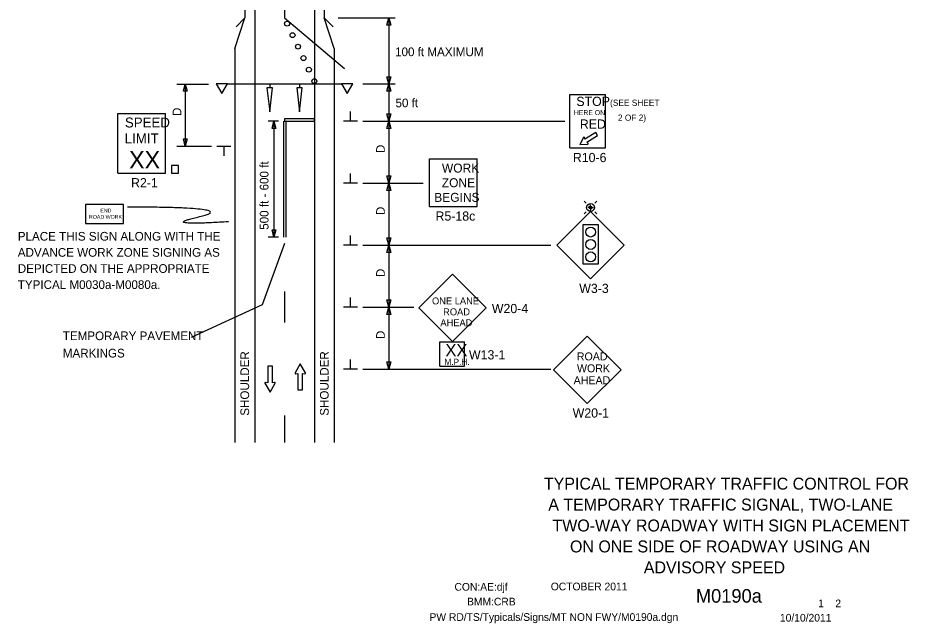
# Model space of a CAD drawing. Extents: x 16739 to 18486, y 7218 to 8208.
# Drawn here: x 16739 to 17457, y 7218 to 7706 of the extents above; entities that cross this region are included whole.
import ezdxf

# ---------------------------------------------------------------- set-up
doc = ezdxf.new("R2010")
doc.units = 0
for name, color, linetype in [('ALI_LEGAL_EX', 7, 'Continuous'), ('BORDER', 7, 'Continuous'), ('BORDER_SIGNAL_WO', 7, 'Continuous'), ('MT_SCRATCH_LEVEL_E', 7, 'Continuous'), ('PAVT_EDGE_EX', 7, 'Continuous'), ('TRAFFIC_SIGNS_PR', 7, 'Continuous'), ('TYPICAL_TEXT_DIMEN_PR', 7, 'Continuous')]:
    doc.layers.add(name, color=color, linetype=linetype)

msp = doc.modelspace()

# ---------------------------------------------------------------- linework, layer by layer
at = {"layer": 'ALI_LEGAL_EX'}
for points in [[(16952.78, 7623.01), (16952.78, 7529.38)], [(16954.78, 7623.01), (16954.78, 7529.38)], [(16953.78, 7485.68), (16953.78, 7460.68)], [(16953.78, 7385.68), (16953.78, 7363.75)]]:
    msp.add_lwpolyline(points, dxfattribs=at)
at = {"layer": 'BORDER'}
msp.add_line((17041.19, 7652.2), (17041.19, 7652.2), dxfattribs=at)
at = {"layer": 'MT_SCRATCH_LEVEL_E'}
for p, q in [((16966.37, 7427.22), (16962.26, 7419.98)), ((16966.37, 7427.22), (16962.26, 7419.98)), ((16970.52, 7419.98), (16966.37, 7427.22)), ((16970.52, 7419.98), (16966.37, 7427.22)), ((16943.98, 7425.26), (16940.24, 7425.26)), ((16940.24, 7425.26), (16940.24, 7412.01)), ((16943.98, 7425.26), (16940.24, 7425.26)), ((16940.24, 7425.26), (16940.24, 7412.01)), ((16943.98, 7412.01), (16943.98, 7425.26)), ((16943.98, 7412.01), (16943.98, 7425.26)), ((16962.74, 7419.29), (16964.52, 7419.61)), ((16962.74, 7419.29), (16964.52, 7419.61)), ((16964.52, 7419.61), (16964.52, 7406.35)), ((16964.52, 7419.61), (16964.52, 7406.35)), ((16968.26, 7406.35), (16968.26, 7419.61)), ((16968.26, 7419.61), (16970.04, 7419.29)), ((16968.26, 7406.35), (16968.26, 7419.61)), ((16968.26, 7419.61), (16970.04, 7419.29)), ((16940.24, 7412.01), (16938.46, 7412.32)), ((16940.24, 7412.01), (16938.46, 7412.32)), ((16945.76, 7412.32), (16943.98, 7412.01)), ((16945.76, 7412.32), (16943.98, 7412.01)), ((16937.98, 7411.64), (16942.13, 7404.4)), ((16937.98, 7411.64), (16942.13, 7404.4)), ((16942.13, 7404.4), (16946.24, 7411.64)), ((16942.13, 7404.4), (16946.24, 7411.64)), ((16964.52, 7406.35), (16968.26, 7406.35)), ((16964.52, 7406.35), (16968.26, 7406.35))]:
    msp.add_line(p, q, dxfattribs=at)
for centre, start, end in [((16962.67, 7419.75), 150.42484, 279.96381), ((16962.67, 7419.75), 150.42484, 279.96381), ((16970.11, 7419.75), 260.03619, 29.77312), ((16970.11, 7419.75), 260.03619, 29.77312), ((16938.39, 7411.86), 80.03619, 209.77312), ((16938.39, 7411.86), 80.03619, 209.77312), ((16945.83, 7411.86), 330.42484, 99.96381), ((16945.83, 7411.86), 330.42484, 99.96381)]:
    msp.add_arc(centre, 0.463, start, end, dxfattribs=at)
at = {"layer": 'PAVT_EDGE_EX'}
for p, q in [((16929.78, 8185.68), (16929.78, 7363.75)), ((16977.78, 8185.68), (16977.78, 7363.75)), ((16921.78, 7837.6), (16921.78, 7706.21)), ((16953.78, 7837.6), (16953.78, 7706.21)), ((16985.78, 7837.6), (16985.78, 7706.21)), ((16913.78, 7681.51), (16921.78, 7706.21)), ((16921.78, 7706.21), (16914.71, 7699.14)), ((16953.78, 7706.21), (17002.19, 7665.59)), ((16985.78, 7706.21), (16992.85, 7699.14)), ((16993.78, 7681.51), (16985.78, 7706.21)), ((16913.78, 7681.51), (16913.78, 7363.75)), ((16993.78, 7681.51), (16993.78, 7363.75))]:
    msp.add_line(p, q, dxfattribs=at)
at = {"layer": 'TRAFFIC_SIGNS_PR'}
for p, q in [((16907.78, 7653.01), (16999.78, 7653.01)), ((16941.78, 7653.01), (16941.78, 7649.99)), ((16965.78, 7653.01), (16965.78, 7649.99)), ((17183.68, 7644.59), (17212.48, 7644.59)), ((17183.68, 7601.39), (17183.68, 7644.59)), ((17198.08, 7644.59), (17198.08, 7644.59)), ((17212.48, 7601.39), (17212.48, 7644.59)), ((16819.37, 7629.06), (16857.77, 7629.06)), ((16819.37, 7581.06), (16819.37, 7629.06)), ((16857.77, 7581.06), (16857.77, 7629.06)), ((17183.68, 7601.39), (17212.48, 7601.39)), ((17070.58, 7554.18), (17070.58, 7592.58)), ((17070.58, 7592.58), (17108.98, 7592.58)), ((17108.98, 7554.18), (17108.98, 7592.58)), ((16819.37, 7581.06), (16857.77, 7581.06)), ((17196.92, 7556.74), (17195.29, 7558.37)), ((17203.77, 7556.74), (17205.39, 7558.37)), ((17070.58, 7554.18), (17108.98, 7554.18)), ((17200.34, 7550.17), (17173.19, 7523.01)), ((17196.92, 7549.89), (17195.29, 7548.27)), ((17200.34, 7553.32), (17198.04, 7553.32)), ((17200.34, 7553.32), (17200.34, 7555.62)), ((17200.34, 7553.32), (17200.34, 7550.17)), ((17200.34, 7553.32), (17202.64, 7553.32)), ((17227.49, 7523.01), (17200.34, 7550.17)), ((17205.39, 7548.27), (17203.77, 7549.89)), ((17173.19, 7523.01), (17200.34, 7495.86)), ((17200.34, 7495.86), (17227.49, 7523.01)), ((17089.01, 7499.48), (17061.85, 7472.33)), ((17116.16, 7472.33), (17089.01, 7499.48)), ((17061.85, 7472.33), (17089.01, 7445.18)), ((17089.01, 7445.18), (17116.16, 7472.33)), ((17197.73, 7449.68), (17170.58, 7422.53)), ((17224.89, 7422.53), (17197.73, 7449.68)), ((17078.98, 7445.12), (17098.83, 7445.12)), ((17078.98, 7425.27), (17078.98, 7445.12)), ((17098.83, 7425.27), (17098.83, 7445.12)), ((17078.98, 7425.27), (17098.83, 7425.27)), ((17170.58, 7422.53), (17197.73, 7395.37)), ((17197.73, 7395.37), (17224.89, 7422.53))]:
    msp.add_line(p, q, dxfattribs=at)
for points in [[(16898.78, 7653.01), (16903.28, 7645.22), (16907.78, 7653.01)], [(16939.53, 7649.99), (16941.78, 7630.57), (16944.03, 7649.99)], [(16963.53, 7649.99), (16965.78, 7630.57), (16968.03, 7649.99)], [(16999.78, 7653.01), (17004.28, 7645.22), (17008.78, 7653.01)], [(16953.78, 7625.01), (16953.78, 7623.01), (16977.78, 7623.01), (16977.78, 7625.01)], [(16862.78, 7581.06), (16868.38, 7581.06), (16868.38, 7587.23), (16862.78, 7587.23)], [(16793.33, 7540.47), (16824.05, 7540.47), (16824.05, 7555.83), (16793.33, 7555.83)], [(17206.4, 7507.56), (17194.4, 7507.56), (17194.4, 7539.56), (17206.4, 7539.56)]]:
    msp.add_lwpolyline(points, close=True, dxfattribs=at)
for points in [[(17198.28, 7605.04), (17197.35, 7606.08), (17206.01, 7611.44), (17204.5, 7613.88), (17195.84, 7608.52), (17195.33, 7609.81)], [(17194.69, 7609.84), (17191.64, 7604.21), (17198.03, 7604.45)]]:
    msp.add_lwpolyline(points, dxfattribs=at)
for centre, radius in [((16955.78, 7701.63), 2), ((16960.18, 7692.37), 2), ((16964.58, 7683.1), 2), ((16968.98, 7673.84), 2), ((16973.38, 7664.57), 2), ((16977.78, 7655.31), 2), ((17200.34, 7553.32), 3.15), ((17200.34, 7553.32), 1.02), ((17200.4, 7533.56), 4), ((17200.4, 7523.56), 4), ((17200.4, 7513.56), 4)]:
    msp.add_circle(centre, radius, dxfattribs=at)
for centre, radius, start, end in [((17195, 7609.67), 0.355, 21.71521, 151.42661), ((17198.01, 7604.8), 0.354, 272.17868, 41.91782)]:
    msp.add_arc(centre, radius, start, end, dxfattribs=at)
msp.add_open_spline([(16908.51, 7541.84), (16850.96, 7538.19), (16918.98, 7553.67), (16827.23, 7553.67)], degree=2, dxfattribs=at)
at = {"layer": 'TYPICAL_TEXT_DIMEN_PR'}
for p, q in [((16997.08, 7706.21), (17042.78, 7706.21)), ((17036.21, 7700.35), (17037.78, 7706.21)), ((17037.78, 7700.35), (17036.21, 7700.35)), ((17037.78, 7706.21), (17037.78, 7653.01)), ((17037.78, 7706.21), (17039.35, 7700.35)), ((17039.35, 7700.35), (17037.78, 7700.35)), ((17037.78, 7653.01), (17036.21, 7658.88)), ((17036.21, 7658.88), (17037.78, 7658.88)), ((17037.78, 7658.88), (17039.35, 7658.88)), ((17039.35, 7658.88), (17037.78, 7653.01)), ((16867.03, 7652.92), (16892.38, 7652.92)), ((16872.21, 7647.06), (16873.78, 7652.92)), ((16873.78, 7652.92), (16873.78, 7602.92)), ((16873.78, 7652.92), (16875.35, 7647.06)), ((17016.78, 7653.01), (17042.78, 7653.01)), ((17036.21, 7647.15), (17037.78, 7653.01)), ((17037.78, 7653.01), (17039.35, 7647.15)), ((17037.78, 7653.01), (17037.78, 7623.01)), ((16873.78, 7647.06), (16872.21, 7647.06)), ((16875.35, 7647.06), (16873.78, 7647.06)), ((17037.78, 7647.15), (17036.21, 7647.15)), ((17039.35, 7647.15), (17037.78, 7647.15)), ((17006.91, 7623.01), (17006.91, 7630.8)), ((17037.78, 7623.01), (17036.21, 7628.88)), ((17036.21, 7628.88), (17037.78, 7628.88)), ((17037.78, 7628.88), (17039.35, 7628.88)), ((17039.35, 7628.88), (17037.78, 7623.01)), ((16948.75, 7623.01), (16940.55, 7623.01)), ((16943.66, 7617.15), (16945.23, 7623.01)), ((16945.23, 7623.01), (16945.23, 7529.38)), ((16945.23, 7623.01), (16946.8, 7617.15)), ((17012.53, 7623.01), (17001.28, 7623.01)), ((17016.78, 7623.01), (17179.49, 7623.01)), ((17036.21, 7617.15), (17037.78, 7623.01)), ((17037.78, 7623.01), (17037.78, 7573.01)), ((17037.78, 7623.01), (17039.35, 7617.15)), ((16945.23, 7617.15), (16943.66, 7617.15)), ((16946.8, 7617.15), (16945.23, 7617.15)), ((17037.78, 7617.15), (17036.21, 7617.15)), ((17039.35, 7617.15), (17037.78, 7617.15)), ((16873.78, 7602.92), (16872.21, 7608.78)), ((16872.21, 7608.78), (16873.78, 7608.78)), ((16873.78, 7608.78), (16875.35, 7608.78)), ((16875.35, 7608.78), (16873.78, 7602.92)), ((16867.03, 7602.92), (16894.99, 7602.92)), ((16899.24, 7602.92), (16910.49, 7602.92)), ((16904.87, 7602.92), (16904.87, 7595.13)), ((17006.91, 7573.01), (17006.91, 7580.8)), ((17037.78, 7573.01), (17036.21, 7578.88)), ((17036.21, 7578.88), (17037.78, 7578.88)), ((17037.78, 7578.88), (17039.35, 7578.88)), ((17039.35, 7578.88), (17037.78, 7573.01)), ((17012.53, 7573.01), (17001.28, 7573.01)), ((17016.78, 7573.01), (17065.34, 7573.01)), ((17036.21, 7567.15), (17037.78, 7573.01)), ((17037.78, 7573.01), (17037.78, 7523.01)), ((17037.78, 7573.01), (17039.35, 7567.15)), ((17037.78, 7567.15), (17036.21, 7567.15)), ((17039.35, 7567.15), (17037.78, 7567.15)), ((16945.23, 7529.38), (16943.66, 7535.25)), ((16943.66, 7535.25), (16945.23, 7535.25)), ((16945.23, 7535.25), (16946.8, 7535.25)), ((16946.8, 7535.25), (16945.23, 7529.38)), ((16948.75, 7529.38), (16940.55, 7529.38)), ((17006.91, 7523.01), (17006.91, 7530.8)), ((17037.78, 7523.01), (17036.21, 7528.88)), ((17036.21, 7528.88), (17037.78, 7528.88)), ((17037.78, 7528.88), (17039.35, 7528.88)), ((17039.35, 7528.88), (17037.78, 7523.01)), ((16936.01, 7475.01), (16953.91, 7524.73)), ((17012.53, 7523.01), (17001.28, 7523.01)), ((17016.78, 7523.01), (17168.45, 7523.01)), ((17036.21, 7517.15), (17037.78, 7523.01)), ((17036.21, 7517.15), (17037.78, 7523.01)), ((17037.78, 7523.01), (17037.78, 7473.01)), ((17037.78, 7523.01), (17039.35, 7517.15)), ((17037.78, 7523.01), (17039.35, 7517.15)), ((17037.78, 7517.15), (17036.21, 7517.15)), ((17037.78, 7517.15), (17036.21, 7517.15)), ((17039.35, 7517.15), (17037.78, 7517.15)), ((17039.35, 7517.15), (17037.78, 7517.15)), ((17006.91, 7473.01), (17006.91, 7480.8)), ((17037.78, 7473.01), (17036.21, 7478.88)), ((17036.21, 7478.88), (17037.78, 7478.88)), ((17037.78, 7478.88), (17039.35, 7478.88)), ((17039.35, 7478.88), (17037.78, 7473.01)), ((16878.77, 7448.84), (16936.01, 7475.01)), ((17012.53, 7473.01), (17001.28, 7473.01)), ((17016.78, 7473.01), (17057.86, 7473.01)), ((17036.21, 7467.15), (17037.78, 7473.01)), ((17037.78, 7473.01), (17037.78, 7423.01)), ((17037.78, 7473.01), (17039.35, 7467.15)), ((17037.78, 7467.15), (17036.21, 7467.15)), ((17039.35, 7467.15), (17037.78, 7467.15)), ((17006.91, 7423.01), (17006.91, 7430.8)), ((17037.78, 7423.01), (17036.21, 7428.88)), ((17036.21, 7428.88), (17037.78, 7428.88)), ((17037.78, 7428.88), (17039.35, 7428.88)), ((17039.35, 7428.88), (17037.78, 7423.01)), ((17012.53, 7423.01), (17001.28, 7423.01)), ((17016.78, 7423.01), (17168.45, 7423.01))]:
    msp.add_line(p, q, dxfattribs=at)

# ---------------------------------------------------------------- texts
at = {"layer": 'BORDER'}
for s, p in [('TYPICAL TEMPORARY TRAFFIC CONTROL FOR', (17162.75, 7325.83)), ('A TEMPORARY TRAFFIC SIGNAL, TWO-LANE', (17166.27, 7308.94)), ('TWO-WAY ROADWAY WITH SIGN PLACEMENT', (17169.63, 7292.06)), ('ON ONE SIDE OF ROADWAY USING AN', (17183.75, 7275.17)), ('ADVISORY SPEED', (17243.23, 7258.28))]:
    msp.add_text(s, height=9.6347, dxfattribs=at).set_placement(p)
at = {"layer": 'BORDER_SIGNAL_WO'}
for s, height, p in [('CON:AE:djf', 6.2, (17090.69, 7244.31)), ('    OCTOBER 2011    ', 6.2, (17159.08, 7244.59)), ('    M0190a    ', 11, (17268.86, 7234.63)), ('BMM:CRB   ', 6.2, (17100.81, 7232.42)), (' 1    2 ', 6.2, (17381.45, 7230.95)), ('PW RD/TS/Typicals/Signs/MT NON FWY/M0190a.dgn     ', 6.2, (17070.55, 7219.96)), ('10/10/2011    ', 6.2, (17352.93, 7219.38))]:
    msp.add_text(s, height=height, dxfattribs=at).set_placement(p)
at = {"layer": 'TRAFFIC_SIGNS_PR'}
for s, height, p in [('STOP', 7.44, (17188.88, 7635.25)), ('HERE ON', 4, (17186.88, 7627.9)), ('SPEED', 8, (16825.13, 7617.92)), ('RED', 7.44, (17191.69, 7616.94)), ('LIMIT', 8, (16824.97, 7605.12)), ('XX', 14.031, (16828.48, 7584.82)), ('R10-6', 7.44, (17186.06, 7589.95)), ('WORK', 7.217, (17080.57, 7581.55)), ('R2-1', 7.44, (16830.04, 7569.62)), ('ZONE', 7.217, (17080.46, 7569.74)), ('BEGINS', 7.217, (17074.38, 7557.93)), ('END', 3.065, (16805.33, 7549.37)), ('R5-18c', 7.44, (17075.39, 7542.74)), ('ROAD WORK', 3.065, (16796.21, 7544.26)), ('PLACE THIS SIGN ALONG WITH THE', 7, (16738.81, 7526.65)), ('ADVANCE WORK ZONE SIGNING AS', 7, (16738.81, 7513.65)), ('DEPICTED ON THE APPROPRIATE', 7, (16738.81, 7500.65)), ('TYPICAL M0030a-M0080a.', 7, (16738.81, 7487.65)), ('W3-3', 7.44, (17191.21, 7484.42)), ('ONE LANE', 5.6, (17072.59, 7475.2)), ('ROAD', 5.6, (17081.54, 7466.4)), ('W20-4', 7.44, (17120.79, 7468.16)), ('AHEAD', 5.6, (17079.3, 7457.6)), ('XX', 9.925, (17083.38, 7433.33)), ('W13-1', 7.44, (17102.36, 7430.81)), ('ROAD', 6.4, (17189.28, 7430.06)), ('M.P.H.', 4.961, (17082.6, 7426.37)), ('WORK', 6.4, (17189.39, 7420.46)), ('AHEAD', 6.4, (17186.7, 7410.86)), ('W20-1', 7.44, (17185.91, 7383.94))]:
    msp.add_text(s, height=height, dxfattribs=at).set_placement(p)
at = {"layer": 'TYPICAL_TEXT_DIMEN_PR'}
for s, height, p in [('100 ft MAXIMUM', 7, (17042.82, 7675.42)), ('50 ft', 7, (17043.16, 7634.22)), ('(SEE SHEET', 5, (17216.07, 7635.33)), ('2 OF 2)', 5, (17222.41, 7623.33)), ('TEMPORARY PAVEMENT', 7, (16775.07, 7446.38)), ('MARKINGS', 7, (16775.07, 7432.38))]:
    msp.add_text(s, height=height, dxfattribs=at).set_placement(p)
for s, p in [('D', (16870.56, 7627.14)), ('D', (17034.56, 7597.23)), ('500 ft - 600 ft', (16940.83, 7535.4)), ('D', (17034.56, 7547.23)), ('D', (17034.56, 7497.23)), ('D', (17034.56, 7447.23)), ('SHOULDER', (16925.2, 7385.43)), ('SHOULDER', (16989.31, 7385.43))]:
    msp.add_text(s, height=7, rotation=90, dxfattribs=at).set_placement(p)

doc.saveas('drawing.dxf')
